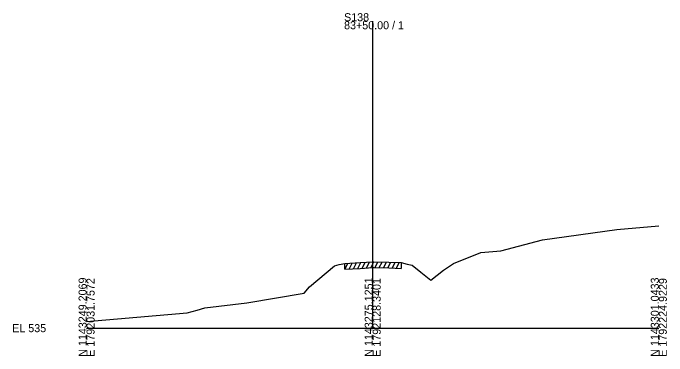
# Model space of a CAD drawing. Extents: x -26 to 1203, y -10 to 19606.
# Drawn here: x -25.7 to 202.8, y 6990.3 to 7110 of the extents above; entities that cross this region are included whole.
import ezdxf

# ---------------------------------------------------------------- set-up
doc = ezdxf.new("R2010")
doc.units = 0
for name, color, linetype in [('RD_EX_Driveway', 7, 'Continuous'), ('RD_GPK_XS_Cell', 7, 'Continuous'), ('RD_XS_ExGround', 7, 'Continuous'), ('RD_XS_ExPaveRet', 7, 'Continuous')]:
    doc.layers.add(name, color=color, linetype=linetype)

msp = doc.modelspace()

# ---------------------------------------------------------------- linework, layer by layer
at = {"layer": 'RD_GPK_XS_Cell'}
for p, q in [((100, 7000), (100, 7107.2)), ((0, 7000), (100, 7000)), ((100, 7000), (200, 7000))]:
    msp.add_line(p, q, dxfattribs=at)
at = {"layer": 'RD_XS_ExGround'}
msp.add_lwpolyline([(0, 7002.32), (35.21, 7005.36), (38.64, 7006.23), (41.32, 7007.09), (56.01, 7008.87), (76.05, 7012.26), (77.96, 7014.48), (86.65, 7021.81), (88.28, 7022.25), (90.32, 7022.55), (95.65, 7022.88), (100, 7023.17), (100.36, 7023.19), (105.65, 7023.03), (109.99, 7022.89), (112.1, 7022.39), (113.76, 7021.99), (116.79, 7019.52), (120.29, 7016.78), (124.79, 7020.25), (128.27, 7022.57), (137.83, 7026.47), (144.77, 7026.99), (159.37, 7030.9), (185.31, 7034.44), (200, 7035.73)], dxfattribs=at)
at = {"layer": 'RD_XS_ExPaveRet'}
for p, q in [((94.82, 7020.83), (95.85, 7022.89)), ((96.32, 7020.92), (97.36, 7022.99)), ((97.82, 7021.02), (98.86, 7023.09)), ((99.32, 7021.12), (100.36, 7023.19)), ((100.82, 7021.18), (101.81, 7023.15)), ((102.32, 7021.13), (103.31, 7023.1)), ((103.82, 7021.08), (104.81, 7023.05)), ((105.32, 7021.04), (106.31, 7023.01)), ((106.82, 7020.99), (107.8, 7022.96)), ((108.32, 7020.94), (109.3, 7022.91)), ((109.99, 7022.89), (109.99, 7020.89)), ((90.32, 7020.55), (91.35, 7022.61)), ((90.32, 7020.55), (90.32, 7022.55)), ((90.32, 7020.55), (95.65, 7020.88)), ((91.82, 7020.64), (92.85, 7022.7)), ((93.32, 7020.73), (94.35, 7022.8)), ((95.65, 7020.88), (100, 7021.17)), ((100, 7021.17), (100.36, 7021.19)), ((100.36, 7021.19), (105.65, 7021.03)), ((105.65, 7021.03), (109.99, 7020.89))]:
    msp.add_line(p, q, dxfattribs=at)

# ---------------------------------------------------------------- texts
at = {"layer": 'RD_EX_Driveway'}
msp.add_text('546.58', height=0.0975, rotation=90, dxfattribs=at).set_placement((100.1, 7023.17))
at = {"layer": 'RD_GPK_XS_Cell'}
for s, p in [('S138', (90, 7107.2)), ('83+50.00 / 1', (90, 7104.4)), ('EL 535', (-26, 6998.6))]:
    msp.add_text(s, height=2.8, dxfattribs=at).set_placement(p)
for s, p in [('N 1143249.2069', (0, 6990)), ('E 1792031.7572', (2.8, 6990)), ('N 1143275.1251', (100, 6990)), ('E 1792128.3401', (102.8, 6990)), ('N 1143301.0433', (200, 6990)), ('E 1792224.9229', (202.8, 6990))]:
    msp.add_text(s, height=2.8, rotation=90, dxfattribs=at).set_placement(p)

doc.saveas('drawing.dxf')
